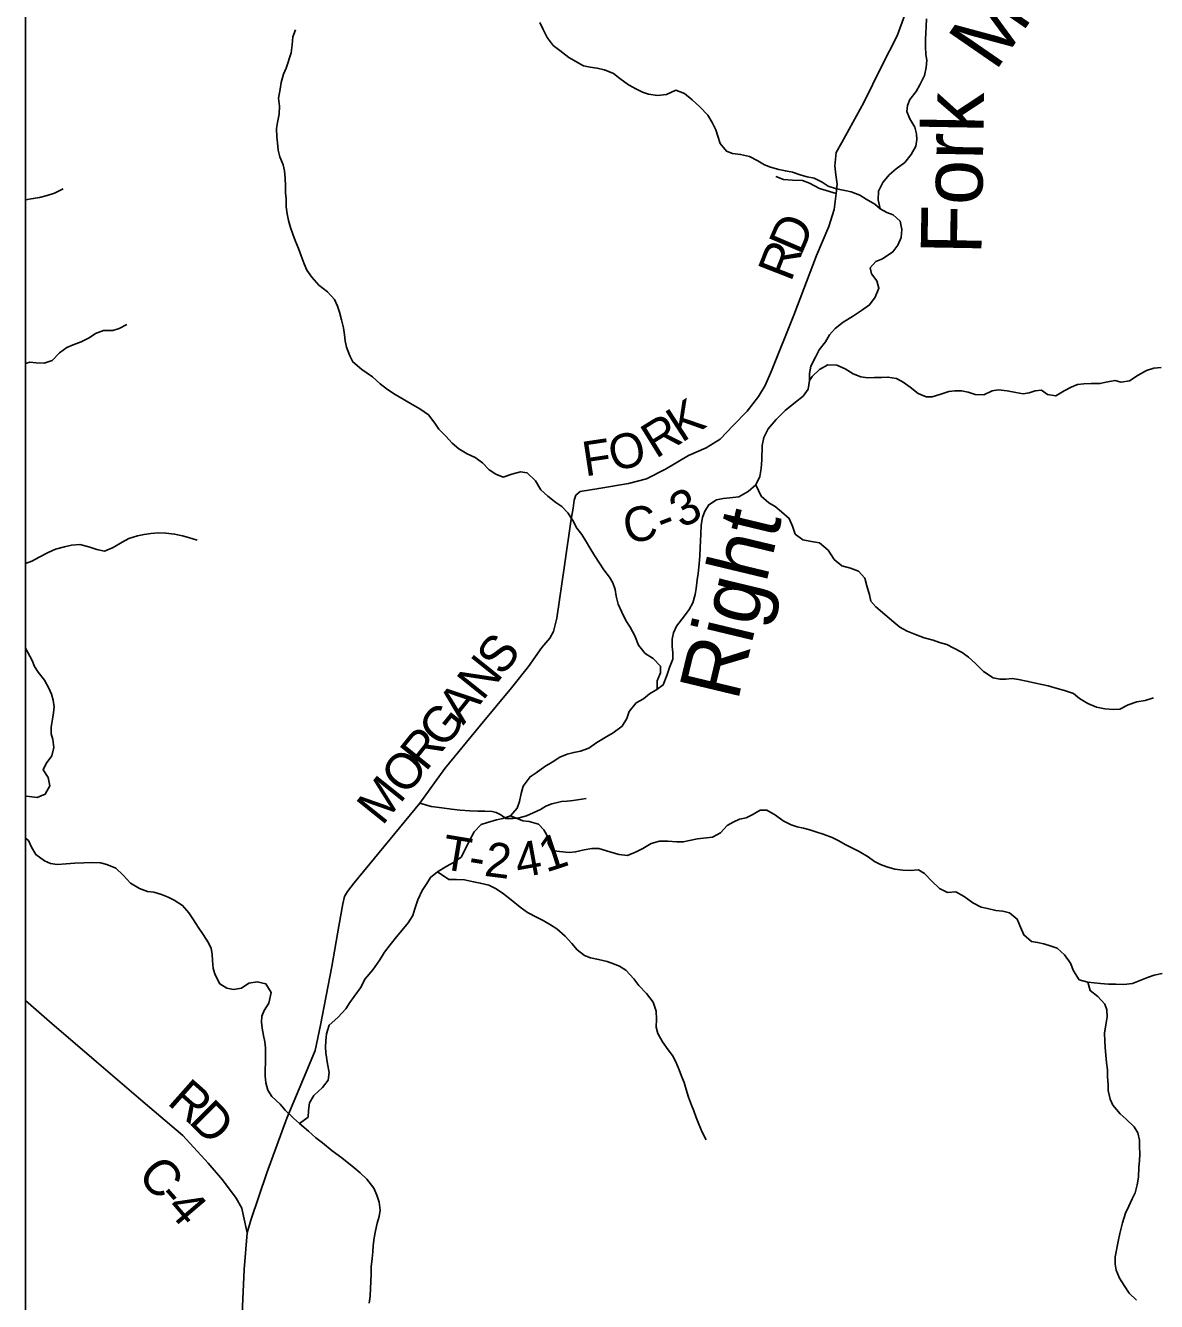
# Model space of a CAD drawing. Extents: x -139 to 835, y 0 to 440.
# Drawn here: x 67.6 to 126.7, y 223.6 to 290.4 of the extents above; entities that cross this region are included whole.
import ezdxf

# ---------------------------------------------------------------- set-up
doc = ezdxf.new("R2010")
doc.units = 0
for name, color, linetype in [('GM_X_County_Road', 7, 'Continuous'), ('GM_X_County_Road_Text', 7, 'Continuous'), ('GM_X_County_Text', 7, 'Continuous'), ('GM_X_Minor_River', 7, 'Continuous'), ('GM_X_Minor_River_Text', 7, 'Continuous'), ('GM_X_Township_Road', 7, 'Continuous'), ('GM_X_Township_Road_Text', 7, 'Continuous'), ('SH_Cut_Line', 7, 'Continuous')]:
    doc.layers.add(name, color=color, linetype=linetype)

msp = doc.modelspace()

# ---------------------------------------------------------------- linework, layer by layer
at = {"layer": 'GM_X_County_Road'}
for points in [[(79.156, 227.236), (79.353, 227.886), (80.193, 230.374), (81.239, 233.222), (82.255, 235.637), (82.711, 236.754), (83.005, 238.09), (83.585, 241.16), (83.964, 243.255), (84.167, 244.435), (84.248, 244.809), (84.403, 245.072), (84.763, 245.527), (88.194, 249.701), (89.494, 251.509), (91.37, 253.77), (92.989, 255.719), (93.864, 256.832), (94.572, 257.838), (94.983, 258.328), (95.177, 258.676), (95.35, 259.374), (95.749, 262.12), (96.093, 264.541), (96.201, 265.119), (96.257, 265.529), (96.348, 265.793), (96.579, 265.984), (97.544, 266.154), (99.093, 266.416), (100.033, 266.647), (101.027, 267.155), (102.227, 267.879), (103.156, 268.279), (103.884, 268.73), (104.564, 269.446), (105.295, 270.186), (105.886, 270.964), (106.235, 271.54), (106.573, 272.296), (107.734, 275.215), (108.923, 278.327), (109.574, 279.852), (109.85, 280.73), (109.961, 281.573), (110.005, 282.055), (109.934, 282.551), (109.889, 283.009), (109.947, 283.709), (110.245, 284.236), (111.397, 286.335), (112.318, 288.207), (113.147, 289.815), (113.54, 290.92)], [(79.156, 227.236), (78.975, 228.095), (78.892, 228.518), (78.581, 229.04), (77.869, 230), (77.132, 230.877), (75.805, 232.314), (73.734, 234.086), (71.287, 236.174), (68.827, 238.276), (67.578, 239.377)], [(78.888, 222.618), (79.007, 225.307), (79.156, 227.236)]]:
    msp.add_lwpolyline(points, dxfattribs=at)
at = {"layer": 'GM_X_County_Text'}
msp.add_lwpolyline([(67.578, 336.518), (67.578, 185.387), (138.399, 185.387)], dxfattribs=at)
at = {"layer": 'GM_X_Minor_River'}
for points in [[(112.253, 280.762), (111.968, 281.012), (111.523, 281.278), (111.193, 281.483), (110.736, 281.652), (110.405, 281.725), (109.973, 281.809), (109.541, 281.954), (109.223, 282.16), (108.804, 282.365), (108.436, 282.45), (108.118, 282.534), (107.673, 282.679), (107.304, 282.752), (106.961, 282.824), (106.517, 282.945), (106.199, 283.066), (105.856, 283.271), (105.424, 283.501), (104.954, 283.61), (104.534, 283.67), (104.217, 283.791), (103.886, 284.177), (103.772, 284.576), (103.658, 284.902), (103.48, 285.277), (103.239, 285.675), (102.833, 286.098), (102.426, 286.461), (102.032, 286.799), (101.575, 286.98), (101.092, 286.751), (100.609, 286.69), (100.151, 286.763), (99.833, 286.872), (99.516, 287.029), (99.096, 287.258), (98.652, 287.584), (98.309, 287.85), (97.851, 288.032), (97.445, 288.128), (97.089, 288.177), (96.746, 288.249), (95.983, 288.684), (95.513, 289.046), (95.158, 289.312), (94.84, 289.735), (94.637, 290.146), (94.459, 290.508)], [(106.034, 267.185), (106.074, 267.643), (106.079, 268.391), (106.171, 268.812), (106.402, 269.269), (106.823, 269.761), (107.295, 270.229), (107.83, 270.659), (108.224, 270.983), (108.493, 271.343), (108.559, 271.789), (108.561, 272.162), (108.627, 272.548), (108.871, 273.005), (109.064, 273.401), (109.396, 273.809), (109.601, 274.182), (109.894, 274.518), (110.314, 274.841), (110.81, 275.139), (111.281, 275.462), (111.701, 275.749), (111.995, 276.157), (112.188, 276.626), (112.077, 277.013), (111.8, 277.364), (111.739, 277.69), (112.033, 278.014), (112.376, 278.157), (112.91, 278.527), (113.178, 278.863), (113.358, 279.272), (113.386, 279.682), (113.3, 280.117), (112.935, 280.456), (112.594, 280.579), (112.253, 280.762), (112.142, 281.245), (112.17, 281.691), (112.388, 282.148), (112.733, 282.544), (113.09, 282.855), (113.536, 283.19), (113.868, 283.61), (114.124, 284.043), (114.164, 284.392), (114.153, 284.694), (114.067, 285.032), (113.804, 285.479), (113.641, 285.854), (113.681, 286.167), (113.81, 286.48), (114.129, 286.9), (114.334, 287.261), (114.578, 287.742), (114.657, 288.163), (114.685, 288.537), (114.649, 288.838), (114.626, 289.249), (114.628, 289.622), (114.643, 289.948), (114.658, 290.309), (114.673, 290.707)], [(100.587, 255.629), (100.591, 255.689), (100.604, 256.088), (100.77, 256.51), (100.77, 256.861), (100.389, 257.26), (99.97, 257.525), (99.614, 257.96), (99.436, 258.443), (99.182, 258.903), (98.954, 259.253), (98.751, 259.676), (98.56, 260.099), (98.459, 260.51), (98.396, 260.872), (98.281, 261.21), (98.104, 261.512), (97.812, 261.887), (97.583, 262.249), (97.316, 262.648), (97.075, 263.047), (96.897, 263.349), (96.656, 263.748), (96.402, 264.074), (96.186, 264.472), (95.932, 264.871), (95.615, 265.197), (95.297, 265.415), (94.89, 265.741), (94.522, 266.079), (94.23, 266.539), (93.798, 266.973), (93.455, 267.01), (92.997, 266.901), (92.552, 266.744), (92.159, 266.889), (91.816, 267.131), (91.46, 267.481), (91.091, 267.771), (90.659, 267.952), (90.227, 268.218), (89.872, 268.52), (89.554, 268.883), (89.186, 269.257), (88.97, 269.571), (88.64, 270.006), (88.182, 270.32), (87.699, 270.598), (87.318, 270.816), (86.899, 271.057), (86.505, 271.323), (86.111, 271.613), (85.718, 271.988), (85.159, 272.362), (84.689, 272.761), (84.523, 273.087), (84.359, 273.534), (84.282, 273.873), (84.257, 274.175), (84.207, 274.549), (84.092, 274.96), (83.991, 275.359), (83.889, 275.673), (83.724, 276.035), (83.356, 276.422), (82.911, 276.772), (82.543, 277.195), (82.276, 277.558), (82.137, 277.896), (81.984, 278.307), (81.845, 278.693), (81.68, 279.116), (81.553, 279.442), (81.426, 279.793), (81.325, 280.155), (81.248, 280.506), (81.211, 280.88), (81.198, 281.291), (81.173, 281.605), (81.173, 281.968), (81.148, 282.378), (81.123, 282.753), (81.046, 283.067), (80.869, 283.49), (80.793, 283.84), (80.755, 284.227), (80.717, 284.541), (80.704, 284.964), (80.755, 285.29), (80.844, 285.725), (80.857, 286.136), (80.794, 286.559), (80.883, 287.03), (80.947, 287.368), (81.062, 287.815), (81.202, 288.129), (81.456, 288.926), (81.52, 289.349), (81.558, 289.76), (81.686, 290.123)], [(67.578, 281.244), (67.98, 281.304), (68.31, 281.364), (68.717, 281.473), (69.099, 281.594), (69.543, 281.811)], [(67.578, 272.689), (67.81, 272.75), (68.128, 272.714), (68.56, 272.702), (68.967, 272.835), (69.348, 273.233), (69.742, 273.511), (70.06, 273.656), (70.492, 273.813), (70.912, 274.031), (71.243, 274.248), (71.662, 274.405), (72.145, 274.405), (72.476, 274.514), (72.87, 274.719)], [(108.559, 271.789), (108.697, 272.011), (109.078, 272.374), (109.523, 272.615), (109.981, 272.603), (110.425, 272.41), (110.845, 272.144), (111.251, 271.987), (111.607, 271.939), (111.95, 271.951), (112.331, 271.951), (112.662, 271.975), (113.107, 271.89), (113.45, 271.709), (113.818, 271.443), (114.238, 271.117), (114.657, 270.936), (114.975, 270.936), (115.369, 271.069), (115.839, 271.213), (116.157, 271.25), (116.5, 271.25), (116.856, 271.189), (117.224, 271.056), (117.669, 271.044), (118.101, 271.25), (118.432, 271.298), (118.889, 271.25), (119.347, 271.165), (119.728, 271.105), (120.046, 271.141), (120.364, 271.25), (120.682, 271.286), (120.999, 271.068), (121.431, 270.984), (121.864, 271.249), (122.232, 271.443), (122.563, 271.576), (122.893, 271.612), (123.287, 271.636), (123.745, 271.636), (124.075, 271.708), (124.52, 271.793), (124.851, 271.708), (125.296, 271.769), (125.741, 272.071), (126.173, 272.324), (126.554, 272.433), (126.948, 272.481)], [(81.896, 232.95), (82.352, 233.283), (82.379, 233.633), (82.42, 234.018), (82.65, 234.403), (83.109, 234.822), (83.39, 235.207), (83.456, 235.604), (83.358, 236.063), (83.273, 236.642), (83.262, 236.944), (83.277, 237.269), (83.304, 237.631), (83.447, 238.088), (83.905, 238.496), (84.326, 238.939), (84.531, 239.264), (84.749, 239.588), (85.081, 240.032), (85.325, 240.501), (85.733, 240.981), (86.091, 241.498), (86.347, 241.906), (86.641, 242.29), (86.973, 242.698), (87.254, 243.034), (87.573, 243.442), (87.816, 243.827), (87.933, 244.164), (88.088, 244.645), (88.306, 245.126), (88.562, 245.487), (88.754, 245.811), (89.111, 246.098), (89.594, 246.409), (89.95, 246.588), (90.345, 246.875), (90.614, 247.38), (90.768, 247.716), (91.025, 248.197), (91.394, 248.581), (91.725, 248.688), (92.194, 248.817), (92.524, 248.9), (92.93, 249.03), (93.275, 249.438), (93.404, 249.787), (93.495, 250.196), (93.599, 250.582), (93.957, 251.074), (94.275, 251.289), (94.733, 251.612), (95.102, 251.839), (95.509, 252.102), (95.891, 252.256), (96.233, 252.351), (96.588, 252.421), (97.033, 252.575), (97.44, 252.862), (97.962, 253.173), (98.292, 253.376), (98.763, 253.723), (99.019, 254.119), (99.136, 254.48), (99.506, 254.948), (99.875, 255.151), (100.193, 255.414), (100.587, 255.629), (100.906, 255.881), (101.099, 256.374), (101.241, 256.795), (101.421, 257.228), (101.411, 257.566), (101.375, 257.892), (101.377, 258.265), (101.443, 258.603), (101.61, 258.951), (102.031, 259.492), (102.274, 259.816), (102.466, 260.164), (102.583, 260.598), (102.636, 260.911), (102.689, 261.369), (102.742, 261.694), (102.796, 262.2), (102.824, 262.622), (102.839, 263.056), (102.854, 263.394), (102.882, 263.779), (102.898, 264.225), (102.964, 264.635), (103.08, 264.96), (103.297, 265.296), (103.704, 265.547), (104.047, 265.629), (104.389, 265.651), (104.871, 265.709), (105.354, 265.983), (105.749, 266.331), (105.955, 266.776), (106.034, 267.185)], [(105.749, 266.331), (106.037, 265.741), (106.431, 265.391), (106.761, 265.197), (107.104, 264.931), (107.498, 264.581), (107.663, 264.182), (107.815, 263.759), (108.209, 263.469), (108.666, 263.373), (109.086, 263.3), (109.53, 262.926), (109.848, 262.442), (110.242, 262.104), (110.699, 261.983), (111.118, 261.826), (111.449, 261.452), (111.563, 261.053), (111.69, 260.582), (111.766, 260.256), (112.032, 259.953), (112.49, 259.555), (112.96, 259.156), (113.29, 258.902), (113.671, 258.685), (114.103, 258.516), (114.561, 258.334), (115.031, 258.214), (115.361, 258.093), (115.743, 257.984), (116.111, 257.803), (116.543, 257.573), (116.873, 257.331), (117.229, 256.993), (117.648, 256.57), (118.156, 256.244), (118.512, 256.172), (118.83, 256.184), (119.148, 256.208), (119.491, 256.159), (119.999, 256.063), (120.38, 255.966), (121.041, 255.821), (121.499, 255.688), (121.893, 255.579), (122.363, 255.422), (122.681, 255.168), (123.113, 254.903), (123.57, 254.721), (124.002, 254.625), (124.472, 254.588), (124.79, 254.613), (125.222, 254.842), (125.667, 254.987), (126.099, 255.059), (126.544, 255.204)], [(67.578, 262.226), (67.906, 262.347), (68.326, 262.577), (68.758, 262.794), (69.152, 262.975), (69.622, 263.096), (69.978, 263.181), (70.423, 263.217), (70.881, 263.096), (71.3, 262.951), (71.707, 262.867), (72.152, 263.06), (72.622, 263.338), (72.978, 263.531), (73.423, 263.676), (73.779, 263.748), (74.122, 263.797), (74.554, 263.821), (74.91, 263.809), (75.367, 263.76), (75.787, 263.664), (76.105, 263.579), (76.549, 263.446)], [(67.578, 250.053), (67.772, 250.047), (68.192, 249.999), (68.611, 250.168), (68.853, 250.603), (68.764, 251.038), (68.497, 251.437), (68.65, 251.775), (68.955, 252.174), (69.057, 252.597), (69.007, 253.019), (68.918, 253.322), (68.918, 253.66), (68.995, 254.083), (69.046, 254.409), (69.071, 254.735), (69.021, 255.086), (68.944, 255.4), (68.805, 255.714), (68.576, 256.125), (68.246, 256.536), (68.056, 256.838), (67.929, 257.152), (67.675, 257.599), (67.578, 257.796)], [(92.93, 249.03), (93.572, 248.778), (93.902, 248.73), (94.385, 248.597), (94.677, 248.295), (94.893, 247.896), (94.893, 247.594), (95.096, 247.219), (95.49, 247.159), (95.998, 247.123), (96.329, 247.147), (96.786, 247.255), (97.18, 247.316), (97.549, 247.316), (97.943, 247.207), (98.299, 247.098), (98.617, 247.002), (99.049, 246.953), (99.506, 247.147), (99.849, 247.328), (100.282, 247.594), (100.727, 247.715), (101.146, 247.715), (101.629, 247.678), (101.959, 247.666), (102.29, 247.751), (102.709, 247.835), (103.027, 247.86), (103.497, 247.92), (103.904, 248.15), (104.26, 248.524), (104.578, 248.705), (104.896, 248.862), (105.252, 248.935), (105.57, 249.092), (105.977, 249.334), (106.332, 249.334), (106.777, 249.068), (107.184, 248.778), (107.603, 248.56), (107.921, 248.464), (108.251, 248.379), (108.581, 248.307), (108.95, 248.174), (109.28, 248.065), (109.738, 247.896), (110.055, 247.739), (110.462, 247.521), (110.843, 247.316), (111.161, 247.159), (111.631, 246.881), (111.949, 246.651), (112.266, 246.482), (112.597, 246.361), (113.016, 246.24), (113.435, 246.192), (113.817, 246.18), (114.261, 246.204), (114.579, 246.011), (114.96, 245.612), (115.354, 245.225), (115.773, 245.032), (116.205, 245.056), (116.637, 244.815), (117.095, 244.488), (117.527, 244.259), (117.87, 244.186), (118.302, 244.089), (118.658, 244.053), (119.014, 243.969), (119.42, 243.63), (119.585, 243.219), (119.763, 242.809), (120.157, 242.47), (120.487, 242.41), (120.805, 242.337), (121.186, 242.217), (121.504, 242.108), (121.885, 241.757), (122.202, 241.334), (122.355, 240.936), (122.659, 240.465), (123.117, 240.332), (123.778, 240.259), (124.184, 240.235), (124.566, 240.223), (124.998, 240.211), (125.443, 240.271), (125.786, 240.404), (126.231, 240.585), (126.574, 240.694), (126.994, 240.79)], [(67.578, 247.868), (67.733, 247.74), (67.885, 247.389), (68.114, 247.002), (68.571, 246.676), (68.889, 246.543), (69.232, 246.495), (69.702, 246.531), (70.16, 246.555), (70.63, 246.579), (71.075, 246.591), (71.494, 246.579), (71.825, 246.495), (72.295, 246.289), (72.689, 245.927), (73.07, 245.504), (73.54, 245.226), (73.959, 245.081), (74.277, 245.033), (74.683, 244.924), (75.027, 244.779), (75.344, 244.622), (75.789, 244.344), (76.119, 243.969), (76.36, 243.595), (76.602, 243.208), (76.856, 242.834), (77.148, 242.398), (77.275, 242.096), (77.338, 241.794), (77.351, 241.468), (77.388, 241.045), (77.49, 240.719), (77.744, 240.248), (78.1, 240.018), (78.443, 239.958), (78.862, 240.03), (79.256, 240.284), (79.689, 240.356), (80.146, 240.248), (80.413, 239.789), (80.298, 239.245), (80.056, 238.858), (79.929, 238.556), (79.916, 238.242), (79.941, 237.928), (80.017, 237.541), (80.081, 237.215), (80.131, 236.901), (80.118, 236.502), (80.118, 236.103), (80.105, 235.789), (80.105, 235.439), (80.143, 235.064), (80.245, 234.69), (80.448, 234.363), (80.892, 233.953), (81.146, 233.651), (81.578, 233.216), (81.896, 232.95), (82.366, 232.551), (82.76, 232.189), (83.103, 231.935)], [(89.111, 246.098), (89.707, 245.697), (90.101, 245.709), (90.52, 245.685), (91.003, 245.588), (91.346, 245.516), (91.791, 245.407), (92.185, 245.214), (92.566, 244.948), (92.959, 244.646), (93.429, 244.259), (93.823, 243.981), (94.319, 243.715), (94.637, 243.558), (95.018, 243.341), (95.348, 243.123), (95.78, 242.737), (96.136, 242.35), (96.415, 242.024), (96.796, 241.734), (97.114, 241.613), (97.533, 241.528), (97.978, 241.408), (98.308, 241.299), (98.626, 241.166), (98.956, 240.961), (99.375, 240.514), (99.642, 240.163), (100.036, 239.74), (100.379, 239.281), (100.544, 238.822), (100.556, 238.399), (100.543, 237.976), (100.632, 237.65), (100.873, 237.215), (101.178, 236.804), (101.394, 236.502), (101.572, 236.176), (101.749, 235.753), (101.876, 235.427), (102.003, 235.089), (102.105, 234.726), (102.231, 234.315), (102.384, 233.905), (102.511, 233.603), (102.638, 233.252), (102.777, 232.914), (102.955, 232.491), (103.158, 232.092)], [(123.117, 240.332), (123.231, 239.897), (123.638, 239.594), (124.006, 239.184), (124.107, 238.882), (124.12, 238.531), (124.056, 238.108), (123.98, 237.673), (123.992, 237.251), (124.017, 236.924), (124.043, 236.526), (124.08, 236.139), (124.131, 235.752), (124.143, 235.39), (124.169, 234.991), (124.181, 234.665), (124.27, 234.218), (124.422, 233.904), (124.803, 233.457), (125.121, 233.167), (125.527, 232.768), (125.718, 232.466), (125.807, 232.079), (125.819, 231.765), (125.832, 231.342), (125.806, 231.016), (125.78, 230.641), (125.755, 230.134), (125.691, 229.747), (125.576, 229.324), (125.424, 229.01), (125.258, 228.624), (125.08, 228.249), (124.927, 227.754), (124.787, 227.198), (124.698, 226.775), (124.545, 225.978), (124.532, 225.591), (124.595, 225.277), (124.76, 224.866), (125.014, 224.479), (125.268, 224.069), (125.662, 223.706)], [(83.103, 231.935), (83.611, 231.512), (84.106, 231.149), (84.741, 230.642), (85.072, 230.364), (85.415, 230.038), (85.783, 229.567), (85.935, 229.192), (86.062, 228.83), (86.113, 228.407), (86.062, 228.081), (85.96, 227.742), (85.871, 227.331), (85.807, 226.969), (85.756, 226.57), (85.73, 226.232), (85.692, 225.894), (85.654, 225.447), (85.641, 225.084), (85.628, 224.685), (85.615, 224.323), (85.589, 223.924), (85.538, 223.55)]]:
    msp.add_lwpolyline(points, dxfattribs=at)
at = {"layer": 'GM_X_Township_Road'}
for points in [[(106.803, 282.463), (107.194, 282.302), (107.663, 282.261), (108.195, 282.255), (108.561, 282.119), (109.09, 281.836), (109.961, 281.573)], [(88.194, 249.701), (88.787, 249.526), (89.344, 249.448), (89.838, 249.382), (90.306, 249.329), (90.812, 249.288), (91.23, 249.271), (91.585, 249.279), (91.965, 249.263), (92.18, 249.213), (92.432, 249.09), (92.683, 248.894), (93.076, 248.89), (93.381, 248.935), (93.762, 249.04), (94.119, 249.193), (94.501, 249.369), (94.769, 249.536), (95.087, 249.653), (95.456, 249.745), (95.595, 249.78), (95.9, 249.807)], [(95.9, 249.807), (96.204, 249.834), (96.89, 249.935)]]:
    msp.add_lwpolyline(points, dxfattribs=at)
at = {"layer": 'SH_Cut_Line'}
msp.add_lwpolyline([(67.578, 336.518), (67.578, 185.387), (295.458, 185.387), (295.458, 319.381), (267.909, 321.538), (228.151, 324.569), (207.436, 326.102), (194.287, 327.176), (177.155, 328.576), (171.559, 329.033), (160.688, 329.921), (158.444, 330.1), (105.67, 333.828), (92.493, 334.759)], close=True, dxfattribs=at)

# ---------------------------------------------------------------- texts
at = {"layer": 'GM_X_County_Road_Text'}
for s, height, rotation, p in [('D', 1.899, 66.82986, (108.12, 278.282)), ('R', 1.9, 68.69544, (107.583, 276.904)), ('K', 1.853, 33.0097, (101.875, 268.512)), ('R', 1.85, 31.71269, (100.525, 267.677)), ('O', 1.817, 14.40824, (98.317, 267.011)), ('F', 1.81, 8.57214, (96.831, 266.775)), ('3', 1.842, 28.1418, (101.883, 264.031)), ('C', 1.812, 10.57603, (99.003, 263.249)), ('-', 1.828, 20.94961, (100.915, 263.642)), ('S', 1.885, 51.74494, (92.498, 256.284)), ('N', 1.885, 51.2561, (91.473, 255.006)), ('A', 1.885, 51.24241, (90.458, 253.741)), ('G', 1.885, 51.24449, (89.443, 252.477)), ('R', 1.885, 51.24321, (88.496, 251.297)), ('O', 1.885, 51.24155, (87.48, 250.032)), ('M', 1.885, 51.24411, (86.229, 248.473)), ('R', 1.869, 318.47894, (74.928, 234.005)), ('D', 1.875, 314.89149, (76.049, 233.014)), ('C', 1.881, 311.68344, (73.366, 230.2)), ('-', 1.881, 311.44069, (74.373, 229.068)), ('4', 1.882, 310.40002, (74.869, 228.506))]:
    msp.add_text(s, height=height, rotation=rotation, dxfattribs=at).set_placement(p)
at = {"layer": 'GM_X_Minor_River_Text'}
for s, height, rotation, p in [('Morgan', 3.1495, 55.43883, (118.266, 287.899)), ('Fork', 3.1735, 88.99665, (117.542, 278.356)), ('Right', 3.1713, 76.49735, (104.803, 254.965))]:
    msp.add_text(s, height=height, rotation=rotation, dxfattribs=at).set_placement(p)
at = {"layer": 'GM_X_Township_Road_Text'}
for s, height, rotation, p in [('T', 1.811, 350.52212, (89.254, 246.273)), ('2', 1.809, 352.81947, (91.514, 245.901)), ('4', 1.812, 10.31836, (93.341, 245.773)), ('1', 1.823, 18.25995, (94.784, 246.056)), ('-', 1.81, 350.78637, (90.666, 246.037))]:
    msp.add_text(s, height=height, rotation=rotation, dxfattribs=at).set_placement(p)

doc.saveas('drawing.dxf')
